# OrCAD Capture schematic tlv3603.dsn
size A
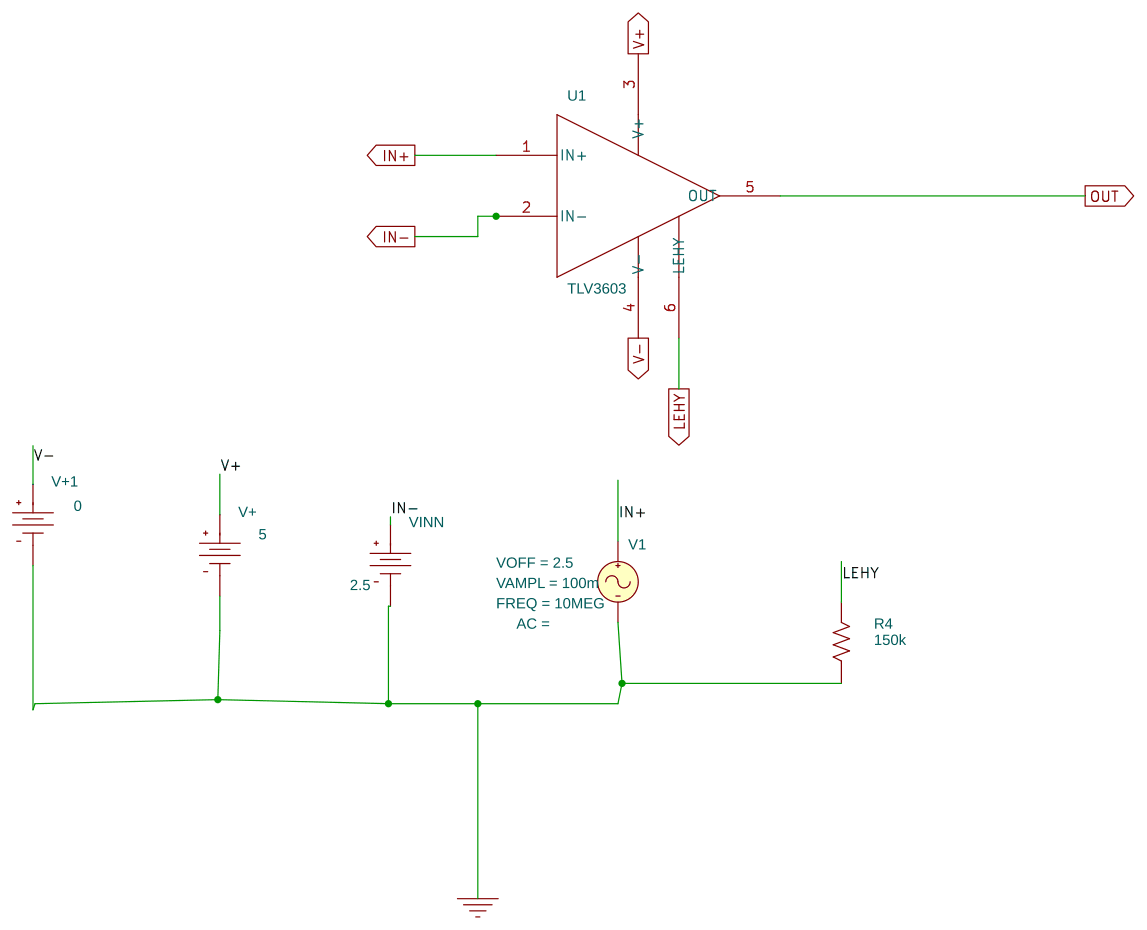
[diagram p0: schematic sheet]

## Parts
R4  150k  [AXRC05]
U1  TLV3603
V1  VSIN
V+  VDC
V+1  VDC
VINN  VDC

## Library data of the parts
R4 = R
U1 = TLV3603
V1 = VSIN: FREQ: 10MEG; VAMPL: 100m; VOFF: 2.5
V+ = VDC: DC: 5
V+1 = VDC: DC: 0
VINN = VDC: DC: 2.5

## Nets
0: R4.1 V1.2(-) V+.1(-) V+1.1(-) VINN.1(-)
IN+: U1.1(IN+) V1.1(+)
IN-: U1.2(IN-) VINN.0(+)
LEHY: R4.2 U1.6(LEHY)
OUT: U1.5(OUT)
V+: U1.3(V+) V+.0(+)
V-: U1.4(V-) V+1.0(+)
